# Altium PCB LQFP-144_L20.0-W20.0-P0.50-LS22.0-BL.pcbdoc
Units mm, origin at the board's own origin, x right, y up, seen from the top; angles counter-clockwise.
Board outline 36.3 x 36.3 mm, 2 copper layers (Top Layer, Bottom Layer), stack 0 mm thick; 1 components, 0 nets, 144 pads, 0 vias.
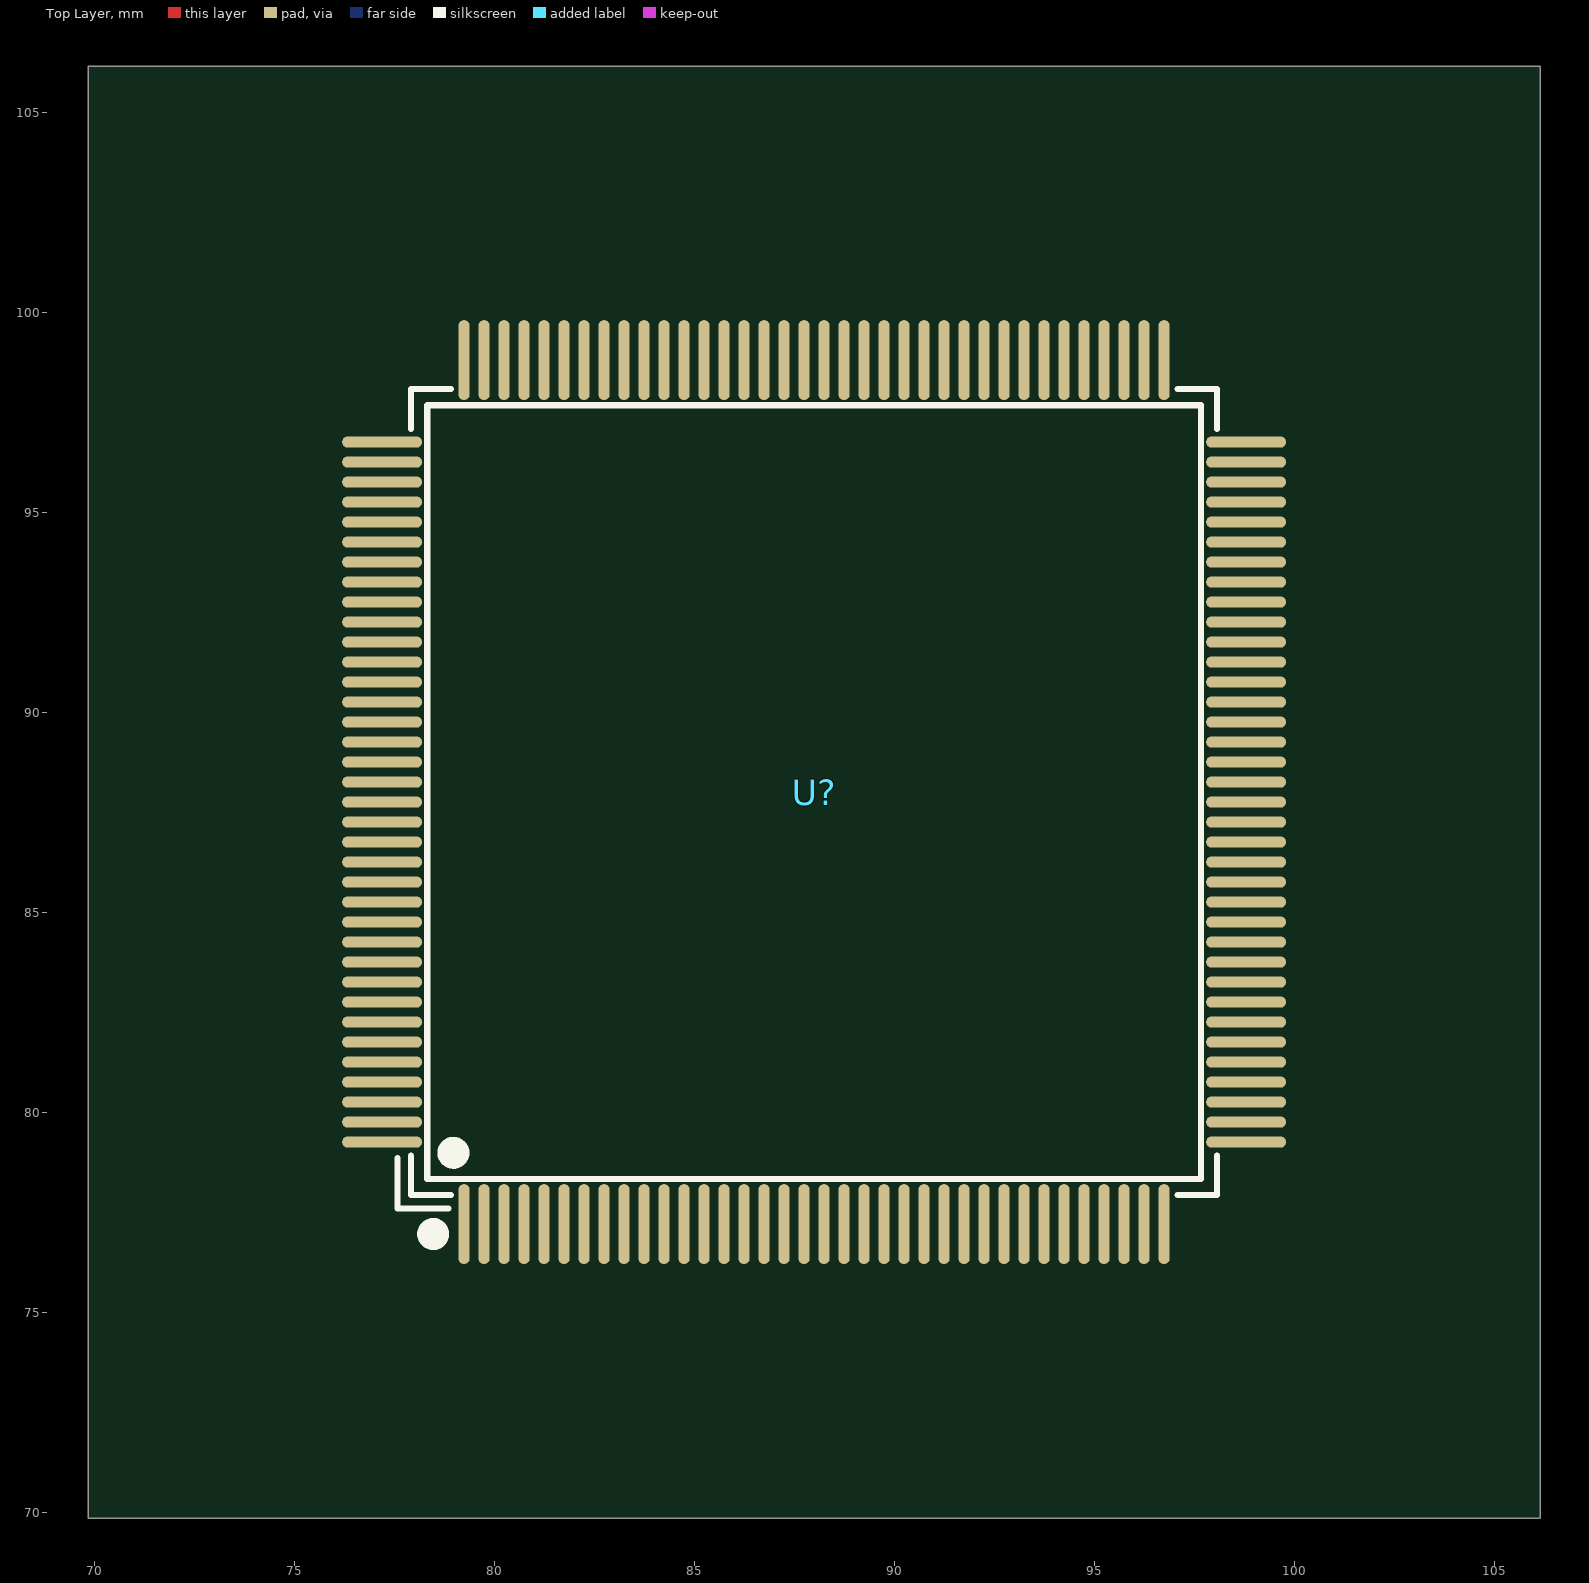
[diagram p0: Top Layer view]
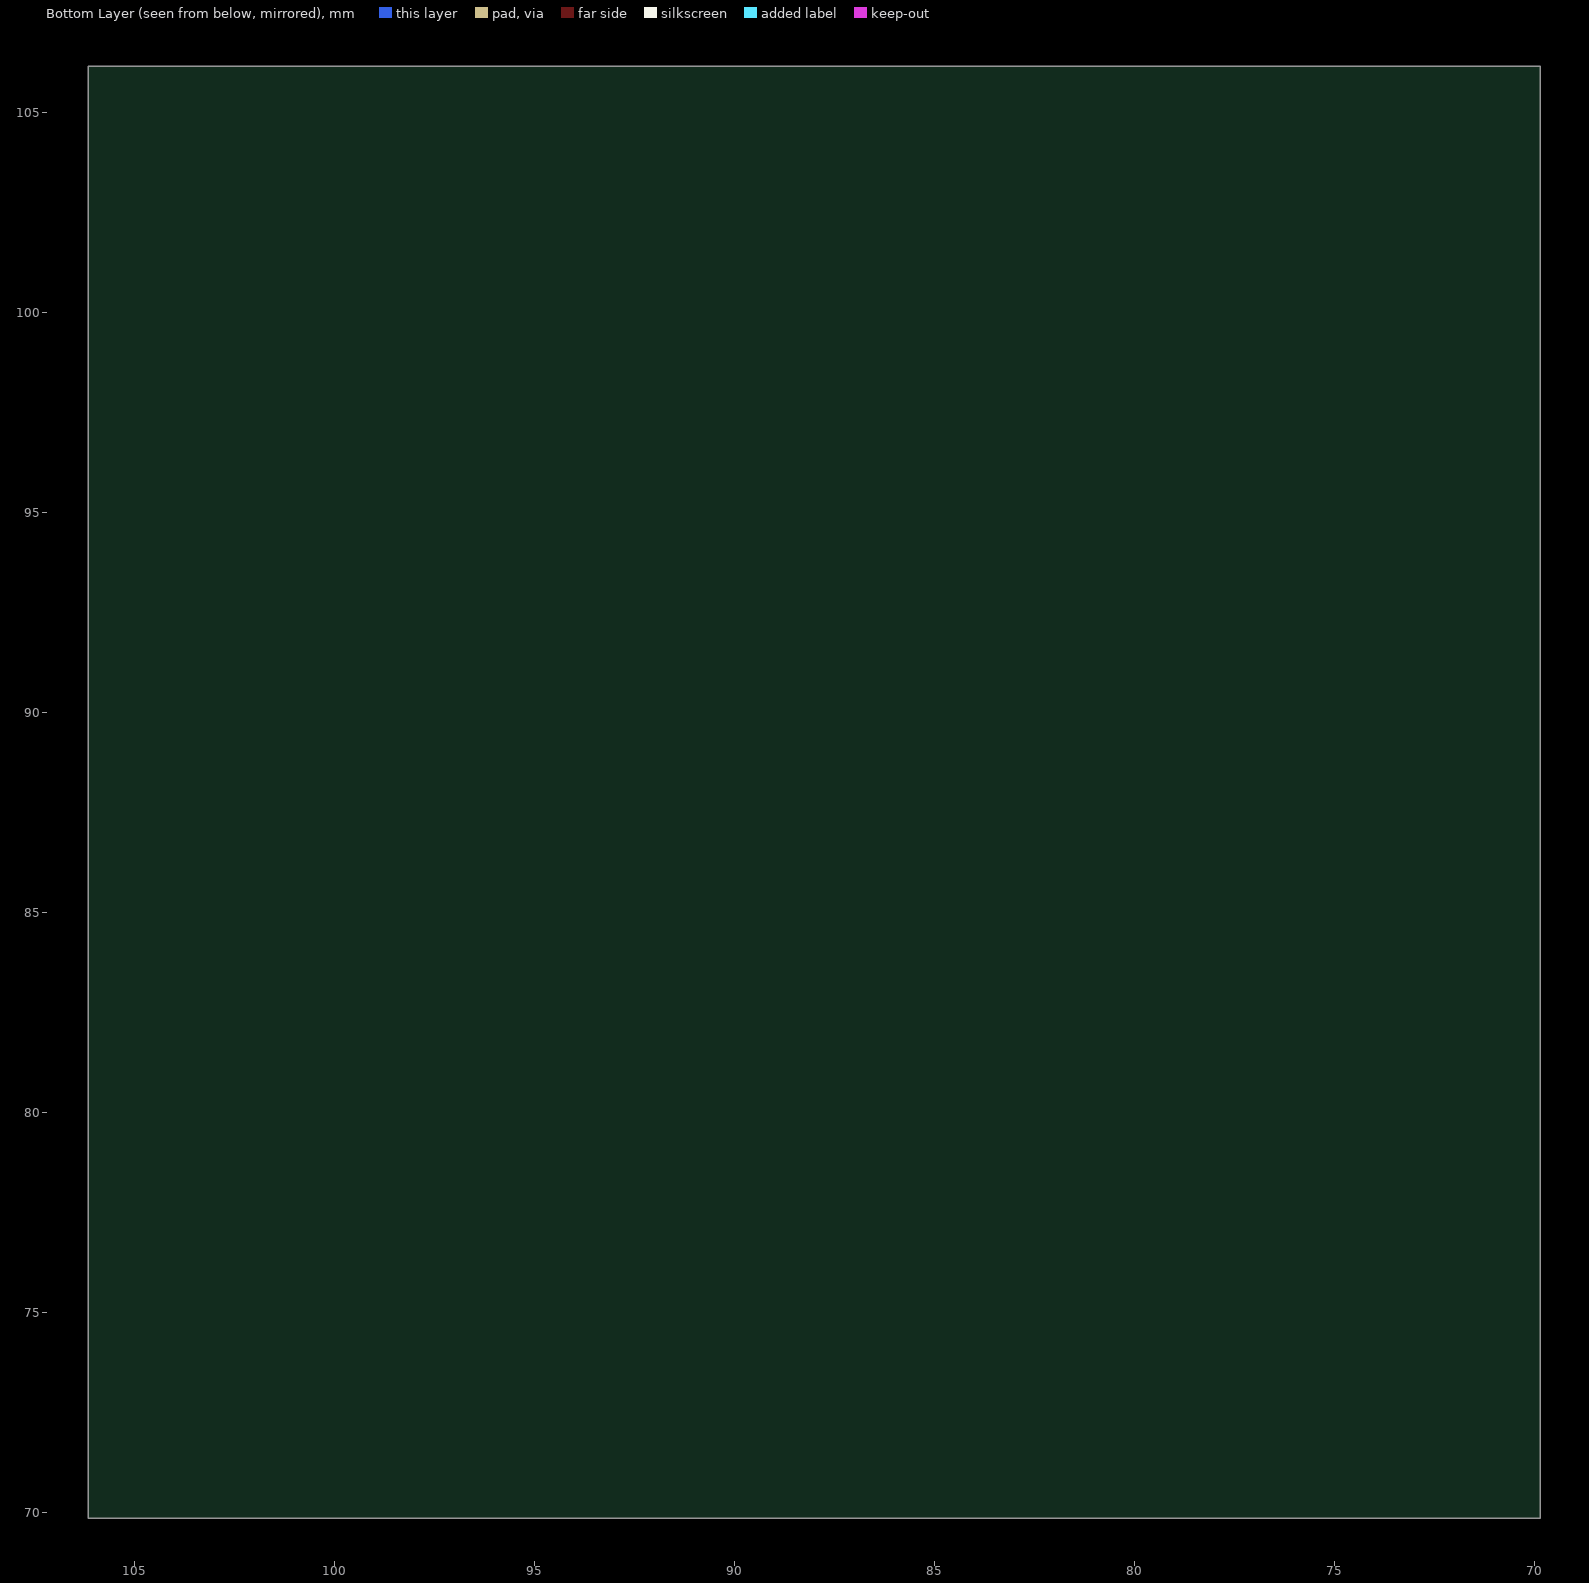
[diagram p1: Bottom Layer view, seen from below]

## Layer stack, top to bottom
Top Layer: signal copper (thickness not stored)
Bottom Layer: signal copper (thickness not stored)

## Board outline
106.15,69.85 69.85,69.85 69.85,106.15 106.15,106.15

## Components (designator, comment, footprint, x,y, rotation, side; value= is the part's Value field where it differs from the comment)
U? "" LQFP-144_L20.0-W20.0-P0.50-LS22.0-BL 88,88 r0 top

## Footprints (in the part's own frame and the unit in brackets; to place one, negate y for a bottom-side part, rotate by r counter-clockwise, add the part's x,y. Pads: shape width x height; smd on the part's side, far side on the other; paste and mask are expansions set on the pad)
LQFP-144_L20.0-W20.0-P0.50-LS22.0-BL [mm]
  oval 0.28x2 smd: 1(-8.75,-10.8) 2(-8.25,-10.8) 3(-7.75,-10.8) 4(-7.25,-10.8) 5(-6.75,-10.8) 6(-6.25,-10.8) 7(-5.75,-10.8) 8(-5.25,-10.8) 9(-4.75,-10.8) 10(-4.25,-10.8) 11(-3.75,-10.8) 12(-3.25,-10.8) 13(-2.75,-10.8) 14(-2.25,-10.8) 15(-1.75,-10.8) 16(-1.25,-10.8) 17(-0.75,-10.8) 18(-0.25,-10.8) 19(0.25,-10.8) 20(0.75,-10.8) 21(1.25,-10.8) 22(1.75,-10.8) 23(2.25,-10.8) 24(2.75,-10.8) 25(3.25,-10.8) 26(3.75,-10.8) 27(4.25,-10.8) 28(4.75,-10.8) 29(5.25,-10.8) 30(5.75,-10.8) 31(6.25,-10.8) 32(6.75,-10.8) 33(7.25,-10.8) 34(7.75,-10.8) 35(8.25,-10.8) 36(8.75,-10.8) 73(8.75,10.8) 74(8.25,10.8) 75(7.75,10.8) 76(7.25,10.8) 77(6.75,10.8) 78(6.25,10.8) 79(5.75,10.8) 80(5.25,10.8) 81(4.75,10.8) 82(4.25,10.8) 83(3.75,10.8) 84(3.25,10.8) 85(2.75,10.8) 86(2.25,10.8) 87(1.75,10.8) 88(1.25,10.8) 89(0.75,10.8) 90(0.25,10.8) 91(-0.25,10.8) 92(-0.75,10.8) 93(-1.25,10.8) 94(-1.75,10.8) 95(-2.25,10.8) 96(-2.75,10.8) 97(-3.25,10.8) 98(-3.75,10.8) 99(-4.25,10.8) 100(-4.75,10.8) 101(-5.25,10.8) 102(-5.75,10.8) 103(-6.25,10.8) 104(-6.75,10.8) 105(-7.25,10.8) 106(-7.75,10.8) 107(-8.25,10.8) 108(-8.75,10.8)
  oval 2x0.28 smd: 37(10.8,-8.75) 38(10.8,-8.25) 39(10.8,-7.75) 40(10.8,-7.25) 41(10.8,-6.75) 42(10.8,-6.25) 43(10.8,-5.75) 44(10.8,-5.25) 45(10.8,-4.75) 46(10.8,-4.25) 47(10.8,-3.75) 48(10.8,-3.25) 49(10.8,-2.75) 50(10.8,-2.25) 51(10.8,-1.75) 52(10.8,-1.25) 53(10.8,-0.75) 54(10.8,-0.25) 55(10.8,0.25) 56(10.8,0.75) 57(10.8,1.25) 58(10.8,1.75) 59(10.8,2.25) 60(10.8,2.75) 61(10.8,3.25) 62(10.8,3.75) 63(10.8,4.25) 64(10.8,4.75) 65(10.8,5.25) 66(10.8,5.75) 67(10.8,6.25) 68(10.8,6.75) 69(10.8,7.25) 70(10.8,7.75) 71(10.8,8.25) 72(10.8,8.75) 109(-10.8,8.75) 110(-10.8,8.25) 111(-10.8,7.75) 112(-10.8,7.25) 113(-10.8,6.75) 114(-10.8,6.25) 115(-10.8,5.75) 116(-10.8,5.25) 117(-10.8,4.75) 118(-10.8,4.25) 119(-10.8,3.75) 120(-10.8,3.25) 121(-10.8,2.75) 122(-10.8,2.25) 123(-10.8,1.75) 124(-10.8,1.25) 125(-10.8,0.75) 126(-10.8,0.25) 127(-10.8,-0.25) 128(-10.8,-0.75) 129(-10.8,-1.25) 130(-10.8,-1.75) 131(-10.8,-2.25) 132(-10.8,-2.75) 133(-10.8,-3.25) 134(-10.8,-3.75) 135(-10.8,-4.25) 136(-10.8,-4.75) 137(-10.8,-5.25) 138(-10.8,-5.75) 139(-10.8,-6.25) 140(-10.8,-6.75) 141(-10.8,-7.25) 142(-10.8,-7.75) 143(-10.8,-8.25) 144(-10.8,-8.75)
  silkscreen extent -10.41,-11.25 10.08,10.08

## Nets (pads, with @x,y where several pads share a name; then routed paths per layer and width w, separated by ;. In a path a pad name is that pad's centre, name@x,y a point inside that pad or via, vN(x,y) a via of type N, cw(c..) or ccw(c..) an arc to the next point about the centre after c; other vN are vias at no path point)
pads on no net: U?.1 U?.2 U?.3 U?.4 U?.5 U?.6 U?.7 U?.8 U?.9 U?.10 U?.11 U?.12 U?.13 U?.14 U?.15 U?.16 U?.17 U?.18 U?.19 U?.20 U?.21 U?.22 U?.23 U?.24 U?.25 U?.26 U?.27 U?.28 U?.29 U?.30 U?.31 U?.32 U?.33 U?.34 U?.35 U?.36 U?.37 U?.38 U?.39 U?.40 U?.41 U?.42 U?.43 U?.44 U?.45 U?.46 U?.47 U?.48 U?.49 U?.50 U?.51 U?.52 U?.53 U?.54 U?.55 U?.56 U?.57 U?.58 U?.59 U?.60 U?.61 U?.62 U?.63 U?.64 U?.65 U?.66 U?.67 U?.68 U?.69 U?.70 U?.71 U?.72 U?.73 U?.74 U?.75 U?.76 U?.77 U?.78 U?.79 U?.80 U?.81 U?.82 U?.83 U?.84 U?.85 U?.86 U?.87 U?.88 U?.89 U?.90 U?.91 U?.92 U?.93 U?.94 U?.95 U?.96 U?.97 U?.98 U?.99 U?.100 U?.101 U?.102 U?.103 U?.104 U?.105 U?.106 U?.107 U?.108 U?.109 U?.110 U?.111 U?.112 U?.113 U?.114 U?.115 U?.116 U?.117 U?.118 U?.119 U?.120 U?.121 U?.122 U?.123 U?.124 U?.125 U?.126 U?.127 U?.128 U?.129 U?.130 U?.131 U?.132 U?.133 U?.134 U?.135 U?.136 U?.137 U?.138 U?.139 U?.140 U?.141 U?.142 U?.143 U?.144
